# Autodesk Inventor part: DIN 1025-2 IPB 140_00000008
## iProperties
Created: 2006-02
Part Number: DIN 1025-2 IPB 140_00000008
Material: Default
Document SubType Name: Modeling
Designer: 40664
Manufacturer: Standard
Standards Organization: Custom
Stock Number: DIN 1025-2 IPB 140
Mass: 11082.7 g
Surface Area: 20865.2 cm^2
Volume: 11082.7 cm^3
Density: 1 g/cm^3
G_L: 2580.000 mm
G_W: 140.000 mm
G_H: 140.000 mm
AFG_Item: IPB 140
CSToolsMass: 11.0
CSToolsVolume: 11082691.0
CSToolsArea: 20865.0
Author: 40664
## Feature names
1. AFG_Detailed_DIN 1025-2 IPB 140_00000008 [Extrusion]
2. AFG_Simplified_DIN 1025-2 IPB 140_00000008 [Extrusion]
